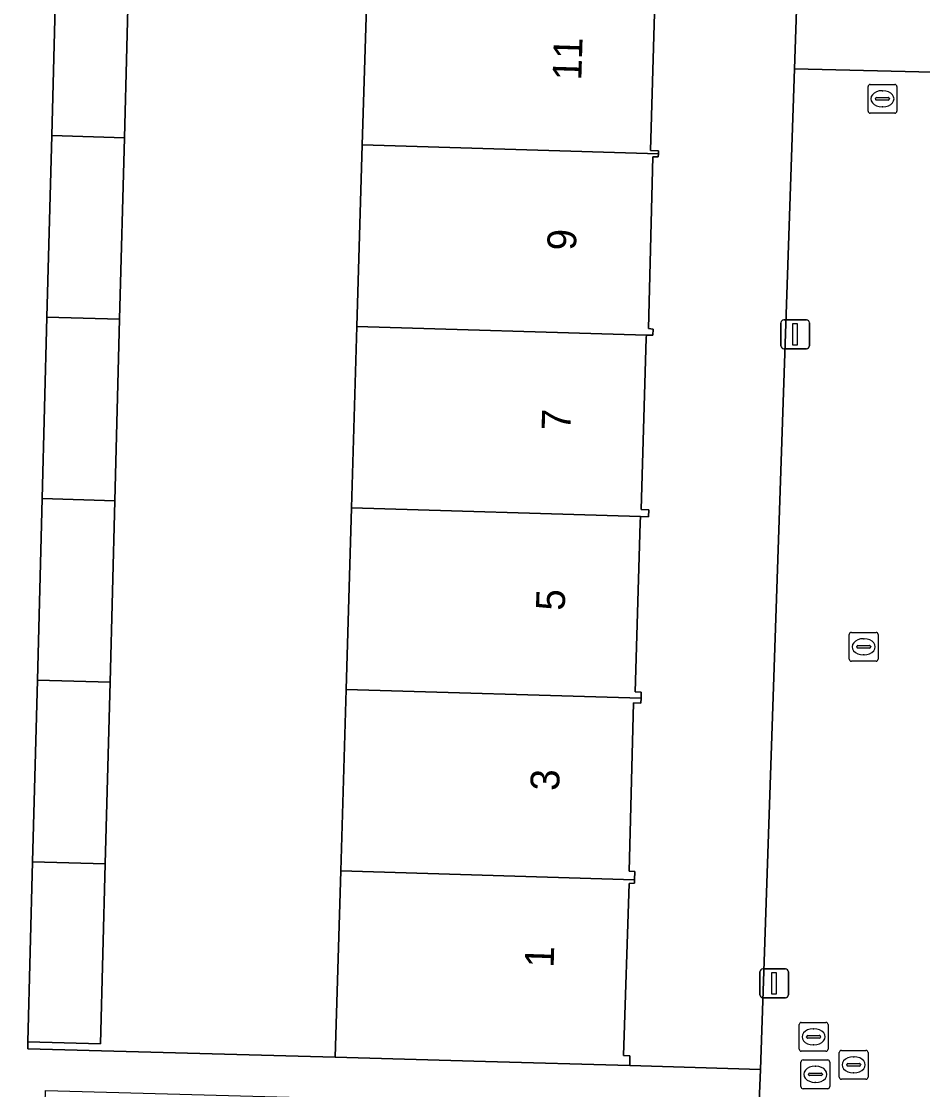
# Model space of a CAD drawing. Extents: x 162082 to 163401, y 388089 to 388636.
# Drawn here: x 162364.41 to 162395.67, y 388363.92 to 388400.98 of the extents above; entities that cross this region are included whole.
import ezdxf

# ---------------------------------------------------------------- set-up
doc = ezdxf.new("R2010")
doc.units = 0
for name, color, linetype in [('IMGEO_Brandkraan', 7, 'Continuous'), ('IMGEO_Erf', 7, 'Continuous'), ('IMGEO_Kolk', 7, 'Continuous'), ('IMGEO_Lichtmast', 7, 'Continuous'), ('IMGEO_Pand', 7, 'Continuous'), ('IMGEO_Pand_nummerreeks', 7, 'Continuous'), ('IMGEO_Rijbaan_lokaal_open', 7, 'Continuous'), ('IMGEO_Rioolput', 7, 'Continuous'), ('IMGEO_Voetpad_open', 7, 'Continuous')]:
    doc.layers.add(name, color=color, linetype=linetype)

msp = doc.modelspace()

# ---------------------------------------------------------------- linework, layer by layer
at = {"layer": 'IMGEO_Brandkraan'}
for p, q in [((162391.45, 388364.024), (162391.45, 388364.876)), ((162391.525, 388364.95), (162392.377, 388364.95)), ((162392.451, 388364.876), (162392.451, 388364.024)), ((162391.752, 388364.493), (162392.15, 388364.493)), ((162391.938, 388364.73), (162391.963, 388364.73)), ((162391.709, 388364.444), (162391.709, 388364.456)), ((162392.147, 388364.407), (162391.749, 388364.407)), ((162391.961, 388364.17), (162391.936, 388364.17)), ((162392.193, 388364.456), (162392.193, 388364.444)), ((162392.377, 388363.95), (162391.525, 388363.95))]:
    msp.add_line(p, q, dxfattribs=at)
for points in [[(162391.45, 388364.024), (162391.45, 388364.876)], [(162391.525, 388364.95), (162392.377, 388364.95)], [(162392.451, 388364.876), (162392.451, 388364.024)], [(162392.377, 388363.95), (162391.525, 388363.95)]]:
    msp.add_lwpolyline(points, dxfattribs=at)
for centre, radius, start, end in [((162391.527, 388364.874), 0.0765, 91.552, 178.448), ((162391.527, 388364.874), 0.0765, 91.552, 178.448), ((162392.375, 388364.874), 0.0765, 1.552, 88.448), ((162392.375, 388364.874), 0.0765, 1.552, 88.448), ((162391.749, 388364.453), 0.0403, 85.8775, 175.7526), ((162392.154, 388364.455), 0.0386, 1.7309, 96.639), ((162391.746, 388364.443), 0.0366, 178.938, 274.7102), ((162392.15, 388364.45), 0.043, 264.8664, 352.4533), ((162391.527, 388364.026), 0.0765, 181.552, 268.448), ((162391.527, 388364.026), 0.0765, 181.552, 268.448), ((162392.375, 388364.026), 0.0765, 271.552, 358.448), ((162392.375, 388364.026), 0.0765, 271.552, 358.448)]:
    msp.add_arc(centre, radius, start, end, dxfattribs=at)
for centre, major_axis, ratio, start_param, end_param in [((162391.937, 388364.45), (-0.387, 0.002), 0.722429, 4.712389, 7.853982), ((162391.962, 388364.45), (-0.39, 0.002), 0.717154, 1.570796, 4.712389)]:
    msp.add_ellipse(centre, major_axis=major_axis, ratio=ratio, start_param=start_param, end_param=end_param, dxfattribs=at)
at = {"layer": 'IMGEO_Erf'}
msp.add_lwpolyline([(162376.236, 388396.697), (162376.423, 388402.994), (162376.61, 388409.292), (162376.8, 388415.702), (162375.2, 388415.749), (162372.174, 388415.837), (162369.148, 388415.926), (162368.481, 388415.945), (162368.456, 388414.976), (162368.314, 388409.541), (162368.148, 388403.242), (162367.983, 388396.945), (162367.818, 388390.647), (162367.652, 388384.348), (162367.487, 388378.051), (162367.322, 388371.753), (162367.158, 388365.51), (162364.636, 388365.576), (162364.63, 388365.331), (162375.298, 388365.051), (162375.489, 388371.508), (162375.676, 388377.805), (162375.863, 388384.102), (162376.05, 388390.4)], close=True, dxfattribs=at)
msp.add_lwpolyline([(162386.406, 388402.464), (162386.231, 388396.501), (162386.509, 388396.493), (162386.506, 388396.389), (162386.502, 388396.28), (162386.315, 388396.285), (162386.164, 388390.33), (162386.319, 388390.303), (162386.313, 388390.092), (162386.088, 388390.099), (162386.085, 388390.004), (162385.911, 388384.051), (162386.177, 388384.04), (162386.157, 388383.793), (162385.881, 388383.801), (162385.875, 388383.584), (162385.703, 388377.718), (162385.908, 388377.712), (162385.904, 388377.498), (162385.9, 388377.329), (162385.646, 388377.336), (162385.491, 388371.494), (162385.683, 388371.491), (162385.675, 388371.203), (162385.671, 388371.077), (162385.491, 388371.073), (162385.296, 388365.102), (162385.519, 388365.095), (162385.509, 388364.752), (162390.042, 388364.615), (162391.221, 388399.33), (162391.581, 388409.926)], dxfattribs=at)
at = {"layer": 'IMGEO_Kolk'}
for p, q in [((162393.776, 388397.87), (162393.776, 388398.722)), ((162393.851, 388398.796), (162394.703, 388398.796)), ((162394.264, 388398.576), (162394.289, 388398.576)), ((162394.777, 388398.722), (162394.777, 388397.87)), ((162394.035, 388398.29), (162394.035, 388398.302)), ((162394.473, 388398.253), (162394.075, 388398.253)), ((162394.078, 388398.339), (162394.476, 388398.339)), ((162394.519, 388398.302), (162394.519, 388398.29)), ((162394.287, 388398.016), (162394.262, 388398.016)), ((162394.703, 388397.796), (162393.851, 388397.796)), ((162393.126, 388378.858), (162393.126, 388379.71)), ((162393.201, 388379.784), (162394.053, 388379.784)), ((162394.127, 388379.71), (162394.127, 388378.858)), ((162393.428, 388379.327), (162393.826, 388379.327)), ((162393.614, 388379.564), (162393.639, 388379.564)), ((162393.385, 388379.278), (162393.385, 388379.29)), ((162393.823, 388379.241), (162393.425, 388379.241)), ((162393.637, 388379.004), (162393.612, 388379.004)), ((162393.869, 388379.29), (162393.869, 388379.278)), ((162394.053, 388378.784), (162393.201, 388378.784)), ((162392.853, 388365.281), (162393.705, 388365.281)), ((162392.778, 388364.355), (162392.778, 388365.207)), ((162393.266, 388365.061), (162393.291, 388365.061)), ((162393.779, 388365.207), (162393.779, 388364.355)), ((162393.037, 388364.775), (162393.037, 388364.787)), ((162393.475, 388364.738), (162393.077, 388364.738)), ((162393.08, 388364.824), (162393.478, 388364.824)), ((162393.289, 388364.501), (162393.264, 388364.501)), ((162393.521, 388364.787), (162393.521, 388364.775)), ((162393.705, 388364.281), (162392.853, 388364.281))]:
    msp.add_line(p, q, dxfattribs=at)
for points in [[(162393.776, 388397.87), (162393.776, 388398.722)], [(162393.851, 388398.796), (162394.703, 388398.796)], [(162394.777, 388398.722), (162394.777, 388397.87)], [(162394.703, 388397.796), (162393.851, 388397.796)], [(162393.126, 388378.858), (162393.126, 388379.71)], [(162393.201, 388379.784), (162394.053, 388379.784)], [(162394.127, 388379.71), (162394.127, 388378.858)], [(162394.053, 388378.784), (162393.201, 388378.784)], [(162392.853, 388365.281), (162393.705, 388365.281)], [(162392.778, 388364.355), (162392.778, 388365.207)], [(162393.779, 388365.207), (162393.779, 388364.355)], [(162393.705, 388364.281), (162392.853, 388364.281)]]:
    msp.add_lwpolyline(points, dxfattribs=at)
for centre, radius, start, end in [((162393.853, 388398.72), 0.0765, 91.552, 178.448), ((162393.853, 388398.72), 0.0765, 91.552, 178.448), ((162394.701, 388398.72), 0.0765, 1.552, 88.448), ((162394.701, 388398.72), 0.0765, 1.552, 88.448), ((162394.075, 388398.299), 0.0403, 85.8775, 175.7526), ((162394.072, 388398.289), 0.0366, 178.938, 274.7102), ((162394.476, 388398.296), 0.043, 264.8664, 352.4533), ((162394.48, 388398.301), 0.0386, 1.7309, 96.639), ((162393.853, 388397.872), 0.0765, 181.552, 268.448), ((162393.853, 388397.872), 0.0765, 181.552, 268.448), ((162394.701, 388397.872), 0.0765, 271.552, 358.448), ((162394.701, 388397.872), 0.0765, 271.552, 358.448), ((162393.203, 388379.708), 0.0765, 91.552, 178.448), ((162393.203, 388379.708), 0.0765, 91.552, 178.448), ((162394.051, 388379.708), 0.0765, 1.552, 88.448), ((162394.051, 388379.708), 0.0765, 1.552, 88.448), ((162393.425, 388379.287), 0.0403, 85.8775, 175.7526), ((162393.83, 388379.289), 0.0386, 1.7309, 96.639), ((162393.422, 388379.277), 0.0366, 178.938, 274.7102), ((162393.826, 388379.284), 0.043, 264.8664, 352.4533), ((162393.203, 388378.86), 0.0765, 181.552, 268.448), ((162393.203, 388378.86), 0.0765, 181.552, 268.448), ((162394.051, 388378.86), 0.0765, 271.552, 358.448), ((162394.051, 388378.86), 0.0765, 271.552, 358.448), ((162392.855, 388365.205), 0.0765, 91.552, 178.448), ((162392.855, 388365.205), 0.0765, 91.552, 178.448), ((162393.703, 388365.205), 0.0765, 1.552, 88.448), ((162393.703, 388365.205), 0.0765, 1.552, 88.448), ((162393.077, 388364.784), 0.0403, 85.8775, 175.7526), ((162393.074, 388364.774), 0.0366, 178.938, 274.7102), ((162393.478, 388364.781), 0.043, 264.8664, 352.4533), ((162393.482, 388364.786), 0.0386, 1.7309, 96.639), ((162392.855, 388364.357), 0.0765, 181.552, 268.448), ((162392.855, 388364.357), 0.0765, 181.552, 268.448), ((162393.703, 388364.357), 0.0765, 271.552, 358.448), ((162393.703, 388364.357), 0.0765, 271.552, 358.448)]:
    msp.add_arc(centre, radius, start, end, dxfattribs=at)
for centre, major_axis, ratio, start_param, end_param in [((162394.263, 388398.296), (-0.387, 0.002), 0.722429, 4.712389, 7.853982), ((162394.288, 388398.296), (-0.39, 0.002), 0.717154, 1.570796, 4.712389), ((162393.613, 388379.284), (-0.387, 0.002), 0.722429, 4.712389, 7.853982), ((162393.638, 388379.284), (-0.39, 0.002), 0.717154, 1.570796, 4.712389), ((162393.265, 388364.781), (-0.387, 0.002), 0.722429, 4.712389, 7.853982), ((162393.29, 388364.781), (-0.39, 0.002), 0.717154, 1.570796, 4.712389)]:
    msp.add_ellipse(centre, major_axis=major_axis, ratio=ratio, start_param=start_param, end_param=end_param, dxfattribs=at)
at = {"layer": 'IMGEO_Lichtmast'}
for p, q in [((162390.752, 388389.725), (162390.752, 388390.525)), ((162390.752, 388390.525), (162390.752, 388389.725)), ((162390.852, 388390.625), (162391.642, 388390.625)), ((162391.642, 388390.625), (162390.852, 388390.625)), ((162391.742, 388390.525), (162391.742, 388389.725)), ((162391.742, 388389.725), (162391.742, 388390.525)), ((162391.642, 388389.625), (162390.852, 388389.625)), ((162390.852, 388389.625), (162391.642, 388389.625)), ((162390.024, 388367.207), (162390.024, 388368.007)), ((162390.024, 388368.007), (162390.024, 388367.207)), ((162390.124, 388368.107), (162390.914, 388368.107)), ((162390.914, 388368.107), (162390.124, 388368.107)), ((162391.014, 388368.007), (162391.014, 388367.207)), ((162391.014, 388367.207), (162391.014, 388368.007)), ((162390.914, 388367.107), (162390.124, 388367.107)), ((162390.124, 388367.107), (162390.914, 388367.107))]:
    msp.add_line(p, q, dxfattribs=at)
for points in [[(162391.172, 388390.5), (162391.322, 388390.5), (162391.322, 388389.75), (162391.172, 388389.75), (162391.172, 388390.5)], [(162390.444, 388367.982), (162390.594, 388367.982), (162390.594, 388367.232), (162390.444, 388367.232), (162390.444, 388367.982)]]:
    msp.add_lwpolyline(points, dxfattribs=at)
for centre, start, end in [((162390.852, 388390.525), 90, 180), ((162390.852, 388390.525), 90, 180), ((162391.642, 388390.525), 0, 90), ((162391.642, 388390.525), 360, 90), ((162390.852, 388389.725), 180, 270), ((162390.852, 388389.725), 180, 270), ((162391.642, 388389.725), 270, 0), ((162391.642, 388389.725), 270, 0), ((162390.124, 388368.007), 90, 180), ((162390.124, 388368.007), 90, 180), ((162390.914, 388368.007), 0, 90), ((162390.914, 388368.007), 360, 90), ((162390.124, 388367.207), 180, 270), ((162390.124, 388367.207), 180, 270), ((162390.914, 388367.207), 270, 0), ((162390.914, 388367.207), 270, 0)]:
    msp.add_arc(centre, 0.1, start, end, dxfattribs=at)
at = {"layer": 'IMGEO_Pand'}
for points in [[(162367.983, 388396.945), (162368.148, 388403.242), (162365.626, 388403.317), (162365.461, 388397.02)], [(162376.423, 388402.994), (162376.236, 388396.697), (162386.506, 388396.389), (162386.509, 388396.493), (162386.231, 388396.501), (162386.406, 388402.464), (162386.674, 388402.456), (162386.681, 388402.687)], [(162367.983, 388396.945), (162365.461, 388397.02), (162365.296, 388390.723), (162367.818, 388390.647)], [(162386.315, 388396.285), (162386.502, 388396.28), (162386.506, 388396.389), (162376.236, 388396.697), (162376.05, 388390.4), (162386.088, 388390.099), (162386.313, 388390.092), (162386.319, 388390.303), (162386.164, 388390.33)], [(162365.131, 388384.424), (162367.652, 388384.348), (162367.818, 388390.647), (162365.296, 388390.723)], [(162386.085, 388390.004), (162386.088, 388390.099), (162376.05, 388390.4), (162375.863, 388384.102), (162385.881, 388383.801), (162386.157, 388383.793), (162386.177, 388384.04), (162385.911, 388384.051)], [(162364.965, 388378.126), (162367.487, 388378.051), (162367.652, 388384.348), (162365.131, 388384.424)], [(162385.881, 388383.801), (162375.863, 388384.102), (162375.676, 388377.805), (162385.904, 388377.498), (162385.908, 388377.712), (162385.703, 388377.718), (162385.875, 388383.584)], [(162367.322, 388371.753), (162367.487, 388378.051), (162364.965, 388378.126), (162364.8, 388371.828)], [(162385.904, 388377.498), (162375.676, 388377.805), (162375.489, 388371.508), (162385.675, 388371.203), (162385.683, 388371.491), (162385.491, 388371.494), (162385.646, 388377.336), (162385.9, 388377.329)], [(162367.322, 388371.753), (162364.8, 388371.828), (162364.636, 388365.576), (162367.158, 388365.51)], [(162385.675, 388371.203), (162375.489, 388371.508), (162375.298, 388365.051), (162380.512, 388364.898), (162385.509, 388364.752), (162385.519, 388365.095), (162385.296, 388365.102), (162385.491, 388371.073), (162385.671, 388371.077)]]:
    msp.add_lwpolyline(points, close=True, dxfattribs=at)
at = {"layer": 'IMGEO_Rijbaan_lokaal_open'}
for points in [[(162463.156, 388408.203), (162434.056, 388408.898), (162432.729, 388408.927), (162394.658, 388409.896), (162391.581, 388409.926), (162391.221, 388399.33), (162397.462, 388399.19), (162409.681, 388398.953), (162410.718, 388398.921), (162421.359, 388398.588), (162426.711, 388398.421), (162427.246, 388398.404), (162432.215, 388398.294), (162439.142, 388397.94), (162439.194, 388399.769), (162462.95, 388399.015)], [(162431.233, 388368.694), (162426.283, 388368.839), (162425.871, 388368.851), (162420.477, 388369.011), (162402.487, 388369.545), (162401.321, 388369.58), (162396.361, 388369.823), (162396.784, 388382.216), (162396.812, 388382.935), (162397.216, 388393.382), (162397.255, 388394.38), (162397.462, 388399.19), (162391.221, 388399.33), (162390.042, 388364.615), (162389.994, 388363.216), (162390.485, 388363.203), (162396.784, 388363.031), (162403.08, 388362.86), (162409.379, 388362.688), (162415.676, 388362.517), (162421.974, 388362.346), (162428.506, 388362.168), (162431.033, 388362.05)]]:
    msp.add_lwpolyline(points, close=True, dxfattribs=at)
at = {"layer": 'IMGEO_Rioolput'}
for p, q in [((162391.387, 388365.324), (162391.387, 388366.176)), ((162391.462, 388366.25), (162392.314, 388366.25)), ((162391.875, 388366.03), (162391.9, 388366.03)), ((162392.388, 388366.176), (162392.388, 388365.324)), ((162391.646, 388365.744), (162391.646, 388365.756)), ((162392.084, 388365.707), (162391.686, 388365.707)), ((162391.689, 388365.793), (162392.087, 388365.793)), ((162392.13, 388365.756), (162392.13, 388365.744)), ((162392.314, 388365.25), (162391.462, 388365.25)), ((162391.898, 388365.47), (162391.873, 388365.47))]:
    msp.add_line(p, q, dxfattribs=at)
for points in [[(162391.387, 388365.324), (162391.387, 388366.176)], [(162391.462, 388366.25), (162392.314, 388366.25)], [(162392.388, 388366.176), (162392.388, 388365.324)], [(162392.314, 388365.25), (162391.462, 388365.25)]]:
    msp.add_lwpolyline(points, dxfattribs=at)
for centre, radius, start, end in [((162391.464, 388366.174), 0.0765, 91.552, 178.448), ((162391.464, 388366.174), 0.0765, 91.552, 178.448), ((162392.312, 388366.174), 0.0765, 1.552, 88.448), ((162392.312, 388366.174), 0.0765, 1.552, 88.448), ((162391.686, 388365.753), 0.0403, 85.8775, 175.7526), ((162391.683, 388365.743), 0.0366, 178.938, 274.7102), ((162392.087, 388365.75), 0.043, 264.8664, 352.4533), ((162392.091, 388365.755), 0.0386, 1.7309, 96.639), ((162391.464, 388365.326), 0.0765, 181.552, 268.448), ((162391.464, 388365.326), 0.0765, 181.552, 268.448), ((162392.312, 388365.326), 0.0765, 271.552, 358.448), ((162392.312, 388365.326), 0.0765, 271.552, 358.448)]:
    msp.add_arc(centre, radius, start, end, dxfattribs=at)
for centre, major_axis, ratio, start_param, end_param in [((162391.874, 388365.75), (-0.387, 0.002), 0.722429, 4.712389, 7.853982), ((162391.899, 388365.75), (-0.39, 0.002), 0.717154, 1.570796, 4.712389)]:
    msp.add_ellipse(centre, major_axis=major_axis, ratio=ratio, start_param=start_param, end_param=end_param, dxfattribs=at)
at = {"layer": 'IMGEO_Voetpad_open'}
msp.add_lwpolyline([(162362.478, 388340.312), (162364.462, 388340.26), (162364.606, 388344.212), (162364.742, 388349.211), (162364.883, 388354.378), (162365.084, 388361.759), (162365.19, 388361.756), (162365.248, 388363.889), (162371.594, 388363.716), (162377.891, 388363.545), (162384.188, 388363.374), (162389.994, 388363.216), (162390.042, 388364.615), (162385.509, 388364.752), (162380.512, 388364.898), (162375.298, 388365.051), (162364.63, 388365.331), (162364.636, 388365.576), (162364.8, 388371.828), (162364.965, 388378.126), (162365.131, 388384.424), (162365.296, 388390.723), (162365.461, 388397.02), (162365.626, 388403.317)], dxfattribs=at)

# ---------------------------------------------------------------- texts
at = {"layer": 'IMGEO_Pand_nummerreeks'}
for s, rotation, p in [('11', 88.2112, (162383.831, 388398.922)), ('9', 88.2126, (162383.645, 388393.02)), ('7', 88.2126, (162383.45, 388386.773)), ('5', 88.2126, (162383.255, 388380.525)), ('3', 88.2112, (162383.061, 388374.277)), ('1', 88.2112, (162382.87, 388368.143))]:
    msp.add_text(s, height=1, rotation=rotation, dxfattribs=at).set_placement(p)

doc.saveas('drawing.dxf')
